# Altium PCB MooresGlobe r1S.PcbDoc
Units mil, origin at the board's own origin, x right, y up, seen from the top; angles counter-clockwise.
Board outline 472.44 x 433.07 mil, 2 copper layers (Top Layer, Bottom Layer), stack 31.54 mil thick; 3 components, 5 nets, 18 pads, 4 vias.
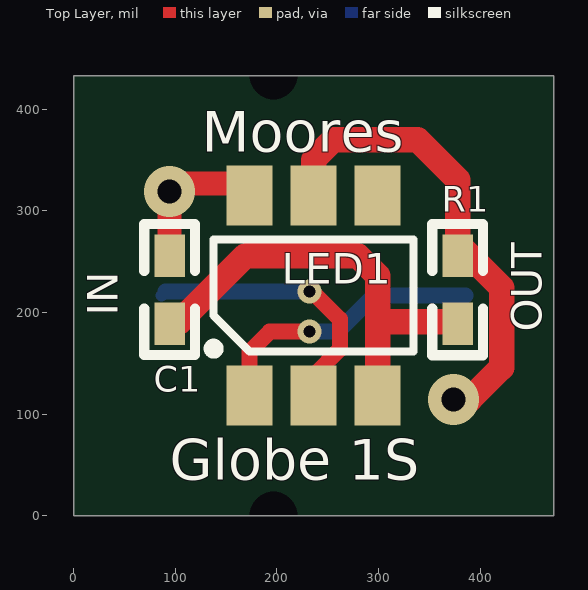
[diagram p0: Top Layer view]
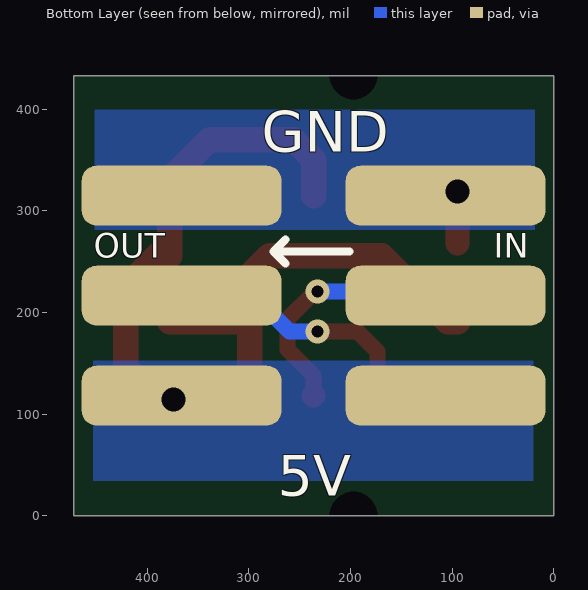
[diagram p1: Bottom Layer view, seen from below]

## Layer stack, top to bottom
Top Layer: signal copper 1.4
Dielectric: core 28.7402, FR-4, Dk 4.8
Bottom Layer: signal copper 1.4

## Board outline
0,0 472.44,0 472.44,433.07 0,433.07

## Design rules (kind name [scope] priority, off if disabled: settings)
Clearance [All] p1: gap=10
HoleSize [All] p1: absolutevalues=TRUE maxlimit=118.11 minlimit=11.81 maxpercent=80.000 minpercent=20.000
MinimumSolderMaskSliver [All] p1: minsoldermaskwidth=6
PlaneClearance [All] p1: clearance=10
PolygonConnect [All] p1: connectstyle=Direct reliefconductorwidth=59.06 reliefentries=4 polygonreliefangle="90 Angle" airgapwidth=10
RoutingVias [All] p1: holewidth=15.75 width=23.62 viastyle="Through Hole" minholewidth=11.81 minwidth=23.62 maxholewidth=39.37 maxwidth=50
SilkToSilkClearance [All] p1 off: silktosilkclearance=0
SilkToSolderMaskClearance [IsPad] p1: minsilkscreentomaskgap=4 clearancetoexposedcopper=TRUE
SolderMaskExpansion [All] p1: expansion=4
Width [All] p1: maxlimit=50 minlimit=10 preferedwidth=10 minimp=50.000000 maximp=50.000000 favimp=50.000000
23 further rules are at their usual default settings.

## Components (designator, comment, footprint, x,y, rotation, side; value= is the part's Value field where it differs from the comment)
C1 "100n" ARA_0603 94.49,188.98 r90 top
LED1 "WS2812" PLCC6-IPC 236.22,216.54 r90 top locked
R1 "100R" ARA_0603 377.95,255.91 r270 top

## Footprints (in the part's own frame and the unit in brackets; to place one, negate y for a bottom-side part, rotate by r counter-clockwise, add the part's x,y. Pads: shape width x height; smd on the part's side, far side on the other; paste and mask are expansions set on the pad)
ARA_0603 [mil]
  rect 42x30 smd: 1(0,0) 2(66.91,0)
  silkscreen extent -31,-25 98,25, body extent 0,-16 67,16, height 20
PLCC6-IPC [mm] "Leaded Chip Carrier, 12-Leads, Body 9.90x5.40mm, Pitch 1.600mm, IPC Medium Density"
  rect 1.5x1.15 smd: 1(-2.5,1.6) 2(-2.5,0) 3(-2.5,-1.6) 4(2.5,-1.6) 5(2.5,0) 6(2.5,1.6)
  silkscreen extent -1.45,-2.5 1.4,2.62, body extent -2.5,-2.5 2.5,2.5, height 1.61

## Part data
C1: library part CAP, "Capacitor Ceramic 100n 50V Y5V 0603"
LED1: "WorldSemi WS2812 Smart RGB LED"
R1: library part "Res Semi", "Resistor 100R 0.1W 5% 0603"

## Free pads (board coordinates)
  round 0 hole 47.24 unplated: 0(196.85,0) 0(196.85,433.07)
  rrect50% 196.85x59.06 smd far side: 5V(106.3,118.11) 5V(366.14,118.11) DIN(106.3,216.54) DOUT(366.14,216.54) GND(106.3,314.96) GND(366.14,314.96)

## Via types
v1: diameter 50, hole 23.62, Top Layer to Bottom Layer, 2 vias
v2: diameter 23.62, hole 11.81, Top Layer to Bottom Layer, tented both sides, 2 vias

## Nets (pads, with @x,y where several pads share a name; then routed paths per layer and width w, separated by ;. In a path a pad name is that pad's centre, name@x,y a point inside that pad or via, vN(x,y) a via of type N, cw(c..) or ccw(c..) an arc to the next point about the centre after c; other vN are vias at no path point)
5V: LED1.5 pad.5V R1.1 | length 465
  Top Layer w25: LED1.5 236.22,350.39 255.91,370.08 338.58,370.08 377.95,330.71 R1.1 ; v1(374.02,114.17) 389.76,114.17 421.26,145.67 421.26,224.41 R1.1@386.26,259.41
DIN: LED1.2 pad.DIN | length 274.2
  Top Layer w15.75: v2(232.28,220.47) 234.89,220.47 261.97,193.4 261.97,163.54 236.22,137.8 LED1.2
  Bottom Layer w11.81: pad.DIN@86.61,216.54 pad.DIN@90.55,220.47
  Bottom Layer w15.75: pad.DIN@90.55,220.47 v2(232.28,220.47)
DOUT: LED1.1 pad.DOUT | length 282.7
  Top Layer w15.75: LED1.1 173.23,161.42 192.91,181.1 v2(232.28,181.1)
  Bottom Layer w15.75: v2@228.35,181.1 259.84,181.1 295.28,216.54 pad.DOUT@385.83,216.54
GND: C1.2 LED1.6 pad.GND | length 138.1
  Top Layer w23.62: C1.2@94.49,267.7 v1(94.49,318.9) 102.36,326.77 161.42,326.77 LED1.6
NetC1_1: C1.1 LED1.3 R1.2 | length 416.9
  Top Layer w25: C1.1@94.49,190.96 104.35,190.96 169.29,255.91 279.53,255.91 299.21,236.22 LED1.3@299.21,137.8 ; 299.21,190.96 R1.2@377.95,190.96
pads on no net: LED1.4

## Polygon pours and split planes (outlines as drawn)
GND on Bottom Layer "Bottom Layer-GND" (solid, pour order 4): 18.47,281.5 18.47,399.61 451.54,399.61 451.54,281.5 18.47,281.5
5V on Bottom Layer "Bottom Layer-5V" (solid, pour order 3): 453.13,152.7 453.13,34.59 20.06,34.59 20.06,152.7 453.13,152.7

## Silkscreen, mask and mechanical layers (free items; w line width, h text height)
Top Overlay:
  text "Moores" at 125.98,358.27 h40
  text "IN" at 43.31,196.85 h30 r90
  text "OUT" at 460.63,181.1 h30 r90
  text "Globe 1S" at 94.49,35.43 h40
Bottom Overlay:
  lines w8: 200.79,259.84 275.59,259.84 ; 263.78,248.03 275.59,259.84 ; 263.78,271.65 275.59,259.84
  text "GND" at 287.4,358.27 h40
  text "IN" at 59.06,253.94 h24
  text "OUT" at 452.76,253.94 h24
  text "5V" at 271.65,19.68 h40
Mechanical 1:
  the board outline again, w23.62
Mechanical 2:
  rectangle: 169.29,0 224.41,55.12
  rectangle: 208.66,377.95 263.78,433.07
  region: 0,433.07 0,409.45 86.61,433.07
  region: 0,0 0,23.62 86.61,0
  region: 472.44,0 472.44,23.62 385.83,0
  region: 472.44,433.07 472.44,409.45 385.83,433.07
  text "Top Layer Component Keep Out Areas" at 826.77,157.48 h39.37
Mechanical 3:
  rectangle: 374.02,0 472.44,27.56
  rectangle: 0,0 98.43,29.53
  rectangle: 0,403.54 98.43,433.07
  rectangle: 374.02,405.51 472.44,433.07
  rectangle: 206.69,403.54 265.75,433.07
  rectangle: 206.69,0 265.75,29.53
  text "Bottom Layer Component Keep Out Areas" at 826.77,78.74 h39.37
Drill Drawing:
  lines w3.94: 826.77,-127.95 3120.08,-127.95 ; 826.77,-49.21 3120.08,-49.21 ; 826.77,295.28 3120.08,295.28 ; 826.77,374.02 3120.08,374.02 ; 826.77,452.76 3120.08,452.76 ; 826.77,531.5 3120.08,531.5 ; 826.77,610.24 3120.08,610.24 ; 826.77,688.98 3120.08,688.98 ; 826.77,767.72 3120.08,767.72 ; 826.77,846.46 3120.08,846.46 ; 1318.9,-206.69 1318.9,39.37 ; 1318.9,216.54 1318.9,925.2 ; 0,0 472.44,0 472.44,433.07 0,433.07 0,0 ; 826.77,-206.69 3120.08,-206.69 3120.08,39.37 826.77,39.37 826.77,-206.69 ; 826.77,216.54 826.77,925.2 3120.08,925.2 3120.08,216.54 826.77,216.54
  text ".legend" at 875.98,1131.89 h39.37
  text "BOARD SIZE:" at 846.46,866.14 h39.37
  text "12.00mm x 11.00mm" at 1358.27,866.14 h39.37
  text "LAYERS:" at 846.46,787.4 h39.37
  text "2" at 1358.27,787.4 h39.37
  text "MATERIAL:" at 846.46,708.66 h39.37
  text "FR4 0.8mm" at 1358.27,708.66 h39.37
  text "COPPER:" at 846.46,629.92 h39.37
  text "35um (after plating)" at 1358.27,629.92 h39.37
  text "PTH PLATING:" at 846.46,551.18 h39.37
  text "20um (minimum)" at 1358.27,551.18 h39.37
  text "FINISH:" at 846.46,472.44 h39.37
  text "ROHS HAL" at 1358.27,472.44 h39.37
  text "OVERLAY:" at 846.46,393.7 h39.37
  text "Black, 2 sides" at 1358.27,393.7 h39.37
  text "SOLDER MASK:" at 846.46,314.96 h39.37
  text "White, 2 sides" at 1358.27,314.96 h39.37
  text "PROFILING:" at 846.46,236.22 h39.37
  text "V-Groove" at 1358.27,236.22 h39.37
  text "FILE NAME:" at 846.46,-29.53 h39.37
  text ".Pcb_File_Name_No_Path" at 1358.27,-29.53 h39.37
  text "LAYER:" at 846.46,-108.27 h39.37
  text ".Plot_File_Name" at 1358.27,-108.27 h39.37
  text "PRINT DATE:" at 846.46,-187.01 h39.37
  text ".Print_Date" at 1358.27,-187.01 h39.37
Mechanical 20:
  the board outline again, w3.94

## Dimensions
-39.37,0 to -39.37,433.07 on Mechanical 16
0,-39.37 to 472.44,-39.37 on Mechanical 16
246.06,511.81 to 226.38,511.81 on Mechanical 16
511.81,0 to 511.81,29.53 on Mechanical 16
0,0 to 472.44,0 on Drill Drawing
0,0 to 0,433.07 on Drill Drawing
